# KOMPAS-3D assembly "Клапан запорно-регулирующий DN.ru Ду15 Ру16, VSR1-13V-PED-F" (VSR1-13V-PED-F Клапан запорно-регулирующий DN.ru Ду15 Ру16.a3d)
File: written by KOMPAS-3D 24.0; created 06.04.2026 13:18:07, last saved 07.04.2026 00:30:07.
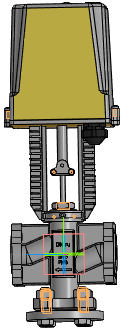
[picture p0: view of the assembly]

Document properties: Автор: R2D2; Полное имя файла: E:\Работа\Зайцев\Солянка\VSR1-13V-PED-F Клапан запорно-регулирующий DN.ru\DN15\DN15 Kv0.16\исходные материалы\VSR1-13V-PED-F Клапан запорно-регулирующий DN.ru Ду15 Ру16.a3d

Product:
- Component [detail]: Фланец Ду15 Ру16  | qty 2  | pos. 1  | Масса: 0.438876; source file: Фланец Ду15 Ру16.m3d
- Component [detail]: Фланец Ду15 Ру16  | qty 1  | pos. 2  | Масса: 0.438876; source file: Фланец Ду15 Ру16.m3d
- Component [detail]: Корпус  | qty 1  | pos. 3  | Масса: 1.53897; Автор: R2D2; source file: Корпус.m3d
- Component [standard]: Заглушка 15-16-1-B-ВЧ40-II ГОСТ 34785-2021  | qty 1  | Материал: ВЧ40 ГОСТ 7293-85 (density 7200 kg/m3); Масса: 0.493926; Раздел спецификации: Стандартные изделия; Рассекать на разрезах: no; additional columns: 15-16-B-1-ВЧ40-II; BOSimple***Material:38d6725a-5efe-48e1-b177-a7817acb862a
- Component [standard]: Болт М12-6gx40 ГОСТ 7796-70  | qty 4  | pos. 4  | Масса: 0.04703; Раздел спецификации: Стандартные изделия; Рассекать на разрезах: no; additional columns: М8x1-6gx12
- Component [standard]: Гайка М12-6H ГОСТ 5915-70  | qty 4  | pos. 5  | Масса: 0.0184; Раздел спецификации: Стандартные изделия; Рассекать на разрезах: no; additional columns: М1,6-6H.12
- Component [detail]: Электропривод  | qty 1  | pos. 6  | Масса: 0.101125; Автор: R2D2; source file: Электропривод.m3d
- Part/product: Клапан запорно-регулирующий DN.ru Ду15 Ру16  | designation VSR1-13V-PED-F
    Масса: 6.1
    Раздел спецификации: Прочие изделия
    Примечание: D090-02879

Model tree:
1. Эскиз:1
2. Болтовое соединение
3. Болтовое соединение (1)
4. Болтовое соединение (2)
5. Болтовое соединение (3)  (with: Грань.Элемент выдавливания:2, Грань.Элемент вращения:1, Грань.Элемент выдавливания:1)  (labels: Грань.Bolt hole.Экземпляр ( 1, 4 ); Грань.Bolt hole.Экземпляр ( 1, 3 ); Грань.Bolt hole.Экземпляр ( 1, 2 ))
     Расстояние = -65; Ориентация = 2; Расстояние = -82; Расстояние = -26; Расстояние = -26; Расстояние = -26; Расстояние = -26; Расстояние = 2

Expressions: VSR1-13V-PED-F
Referenced files in E:\Работа\Зайцев\Солянка\VSR1-13V-PED-F Клапан запорно-регулирующий DN.ru\DN15\DN15 Kv0.16\исходные материалы\: Фланец Ду15 Ру16.m3d, Корпус.m3d, Электропривод.m3d
Referenced files in C:\Program Files\ASCON\KOMPAS-3D v24\Libs\PolynomLib\DATA\vault\Methods\Kompas\3D\: PLib_Flange_Blind_GOST_34785_2100.m3d, PLib_Bolt_1_900.m3d, PLib_Nut_OST92_900.m3d
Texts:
  Фланцы ГОСТ Р 54432
  ВЧ40
  BOSimple***PART:b4ab8050-46da-a315-87a2-4b0d7c838a20***SHORTLOC:B619_EF039B503CC34112[1;16;15;Круглая;II;ВЧ40 ГОСТ 7293-85]
  BOSimple***Material:38d6725a-5efe-48e1-b177-a7817acb862a
  Крепежное изделие ГОСТ
  Программные изделия  и базы данных
  Edge1
  Edge2
  TKR3D
  Справочник стандартных изделий
  Фланец Ду15 Ру16 (1)
  Фланец Ду15 Ру16 (2)
  Фланец Ду15 Ру16 (3)
  Болт М12-6gx40 ГОСТ 7796-70 (1)
  hole1
  hole2
  Гайка М12-6H ГОСТ 5915-70 (1)
  bcut1
  hcut1
  cut1
  Болт М12-6gx40 ГОСТ 7796-70 (2)
  Гайка М12-6H ГОСТ 5915-70 (2)
  Болт М12-6gx40 ГОСТ 7796-70 (3)
  Гайка М12-6H ГОСТ 5915-70 (3)
  Болт М12-6gx40 ГОСТ 7796-70 (4)
  Гайка М12-6H ГОСТ 5915-70 (4)
  Плоскость XY.Начало координат
  Ось Z.Начало координат
  Плоскость ZY.Начало координат
  Плоскость ZX.Начало координат
  Ось Y.Начало координат
  Plane. Начало координат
